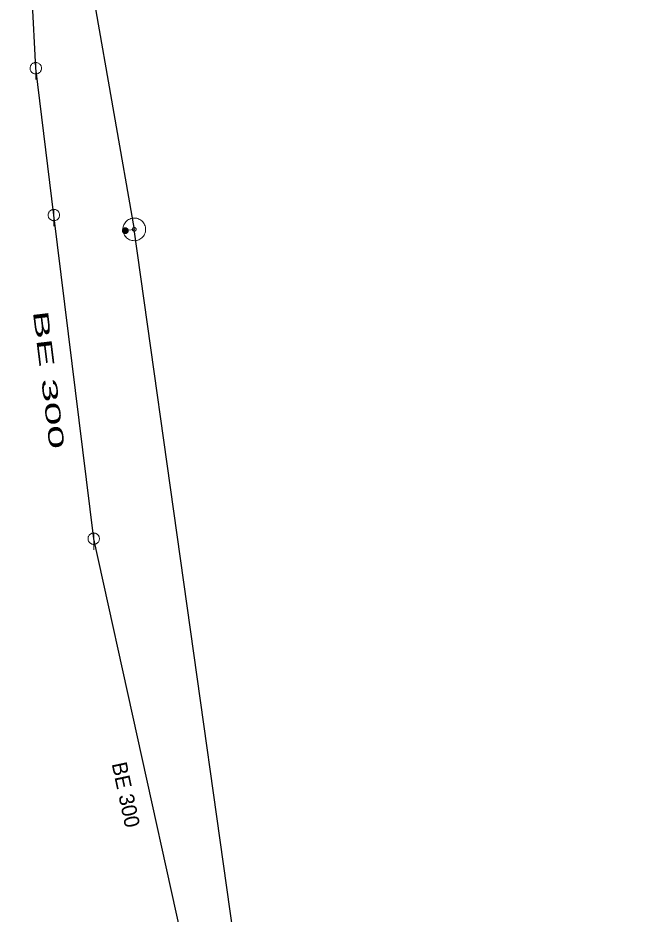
# Model space of a CAD drawing. Extents: x -687515 to -686506, y -974029 to -973461.
# Drawn here: x -687365.89 to -687338.06, y -973760.45 to -973720.93 of the extents above; entities that cross this region are included whole.
import ezdxf
from ezdxf.enums import TextEntityAlignment as Align

# ---------------------------------------------------------------- set-up
doc = ezdxf.new("R2010")
doc.units = 0
doc.header["$LTSCALE"] = 0.27
for name, color, linetype, lineweight in [('1', 7, 'Continuous', 13), ('14', 7, 'Continuous', 25), ('17', 7, 'Continuous', 25), ('22', 7, 'Continuous', 13), ('47', 7, 'Continuous', 13), ('9', 7, 'Continuous', 13)]:
    doc.layers.add(name, color=color, linetype=linetype, lineweight=lineweight)

msp = doc.modelspace()

# ---------------------------------------------------------------- linework, layer by layer
at = {"layer": '14'}
for p, q in [((-687365.103, -973723.149), (-687365.89, -973707.98)), ((-687364.305, -973729.623), (-687365.103, -973723.149)), ((-687362.547, -973743.895), (-687364.305, -973729.623)), ((-687356.89, -973769.55), (-687362.547, -973743.895))]:
    msp.add_line(p, q, dxfattribs=at)
at = {"layer": '14', "lineweight": 13}
msp.add_line((-687361.155, -973730.311), (-687360.759, -973730.255), dxfattribs=at)
at = {"layer": '17'}
for p in [(-687364.062, -973711.454), (-687338.055, -973891.483)]:
    msp.add_line(p, (-687360.759, -973730.255), dxfattribs=at)
at = {"layer": '22'}
for p, q in [((-687365.102, -973722.897), (-687365.103, -973723.641)), ((-687364.304, -973729.371), (-687364.305, -973730.115)), ((-687362.546, -973743.643), (-687362.547, -973744.387))]:
    msp.add_line(p, q, dxfattribs=at)
for points in [[(-687364.851, -973723.149), (-687364.852, -973723.123), (-687364.856, -973723.097), (-687364.862, -973723.071), (-687364.872, -973723.047), (-687364.884, -973723.023), (-687364.898, -973723.001), (-687364.915, -973722.98), (-687364.933, -973722.962), (-687364.954, -973722.945), (-687364.976, -973722.931), (-687365, -973722.919), (-687365.024, -973722.909), (-687365.05, -973722.903), (-687365.076, -973722.899), (-687365.102, -973722.897), (-687365.128, -973722.898), (-687365.154, -973722.902), (-687365.18, -973722.908), (-687365.205, -973722.918), (-687365.228, -973722.93), (-687365.25, -973722.944), (-687365.271, -973722.961), (-687365.289, -973722.979), (-687365.306, -973723), (-687365.32, -973723.022), (-687365.332, -973723.046), (-687365.342, -973723.07), (-687365.349, -973723.096), (-687365.353, -973723.122), (-687365.355, -973723.148), (-687365.354, -973723.174), (-687365.35, -973723.2), (-687365.343, -973723.226), (-687365.333, -973723.251), (-687365.321, -973723.274), (-687365.307, -973723.296), (-687365.29, -973723.317), (-687365.272, -973723.335), (-687365.251, -973723.352), (-687365.229, -973723.366), (-687365.206, -973723.378), (-687365.181, -973723.388), (-687365.155, -973723.395), (-687365.129, -973723.399), (-687365.103, -973723.401), (-687365.077, -973723.4), (-687365.051, -973723.396), (-687365.025, -973723.389), (-687365.001, -973723.379), (-687364.977, -973723.367), (-687364.955, -973723.353), (-687364.934, -973723.336), (-687364.916, -973723.318), (-687364.899, -973723.297), (-687364.885, -973723.275), (-687364.873, -973723.252), (-687364.863, -973723.227), (-687364.857, -973723.201), (-687364.853, -973723.175)], [(-687364.053, -973729.623), (-687364.054, -973729.597), (-687364.058, -973729.571), (-687364.064, -973729.545), (-687364.074, -973729.521), (-687364.086, -973729.497), (-687364.1, -973729.475), (-687364.117, -973729.454), (-687364.135, -973729.436), (-687364.156, -973729.419), (-687364.178, -973729.405), (-687364.202, -973729.393), (-687364.226, -973729.383), (-687364.252, -973729.377), (-687364.278, -973729.373), (-687364.304, -973729.371), (-687364.33, -973729.372), (-687364.356, -973729.376), (-687364.382, -973729.382), (-687364.407, -973729.392), (-687364.43, -973729.404), (-687364.452, -973729.418), (-687364.473, -973729.435), (-687364.491, -973729.453), (-687364.508, -973729.474), (-687364.522, -973729.496), (-687364.534, -973729.52), (-687364.544, -973729.544), (-687364.551, -973729.57), (-687364.555, -973729.596), (-687364.557, -973729.622), (-687364.556, -973729.648), (-687364.552, -973729.674), (-687364.545, -973729.7), (-687364.535, -973729.725), (-687364.523, -973729.748), (-687364.509, -973729.77), (-687364.492, -973729.791), (-687364.474, -973729.809), (-687364.453, -973729.826), (-687364.431, -973729.84), (-687364.408, -973729.852), (-687364.383, -973729.862), (-687364.357, -973729.869), (-687364.331, -973729.873), (-687364.305, -973729.875), (-687364.279, -973729.874), (-687364.253, -973729.87), (-687364.227, -973729.863), (-687364.203, -973729.853), (-687364.179, -973729.841), (-687364.157, -973729.827), (-687364.136, -973729.81), (-687364.118, -973729.792), (-687364.101, -973729.771), (-687364.087, -973729.749), (-687364.075, -973729.726), (-687364.065, -973729.701), (-687364.059, -973729.675), (-687364.055, -973729.649)], [(-687362.295, -973743.895), (-687362.296, -973743.869), (-687362.3, -973743.843), (-687362.306, -973743.817), (-687362.316, -973743.793), (-687362.328, -973743.769), (-687362.342, -973743.747), (-687362.359, -973743.726), (-687362.377, -973743.708), (-687362.398, -973743.691), (-687362.42, -973743.677), (-687362.444, -973743.665), (-687362.468, -973743.655), (-687362.494, -973743.649), (-687362.52, -973743.645), (-687362.546, -973743.643), (-687362.572, -973743.644), (-687362.598, -973743.648), (-687362.624, -973743.654), (-687362.649, -973743.664), (-687362.672, -973743.676), (-687362.694, -973743.69), (-687362.715, -973743.707), (-687362.733, -973743.725), (-687362.75, -973743.746), (-687362.764, -973743.768), (-687362.776, -973743.792), (-687362.786, -973743.816), (-687362.793, -973743.842), (-687362.797, -973743.868), (-687362.799, -973743.894), (-687362.798, -973743.92), (-687362.794, -973743.946), (-687362.787, -973743.972), (-687362.777, -973743.997), (-687362.765, -973744.02), (-687362.751, -973744.042), (-687362.734, -973744.063), (-687362.716, -973744.081), (-687362.695, -973744.098), (-687362.673, -973744.112), (-687362.65, -973744.124), (-687362.625, -973744.134), (-687362.599, -973744.141), (-687362.573, -973744.145), (-687362.547, -973744.147), (-687362.521, -973744.146), (-687362.495, -973744.142), (-687362.469, -973744.135), (-687362.445, -973744.125), (-687362.421, -973744.113), (-687362.399, -973744.099), (-687362.378, -973744.082), (-687362.36, -973744.064), (-687362.343, -973744.043), (-687362.329, -973744.021), (-687362.317, -973743.998), (-687362.307, -973743.973), (-687362.301, -973743.947), (-687362.297, -973743.921)]]:
    msp.add_lwpolyline(points, close=True, dxfattribs=at)
at = {"layer": '47'}
for points in [[(-687360.656, -973730.744), (-687360.606, -973730.73), (-687360.557, -973730.712), (-687360.51, -973730.688), (-687360.466, -973730.66), (-687360.425, -973730.627), (-687360.388, -973730.59), (-687360.356, -973730.549), (-687360.327, -973730.505), (-687360.303, -973730.459), (-687360.283, -973730.41), (-687360.27, -973730.36), (-687360.262, -973730.308), (-687360.259, -973730.256), (-687360.261, -973730.204), (-687360.269, -973730.152), (-687360.283, -973730.102), (-687360.301, -973730.053), (-687360.325, -973730.005), (-687360.353, -973729.962), (-687360.386, -973729.921), (-687360.423, -973729.884), (-687360.464, -973729.851), (-687360.508, -973729.822), (-687360.554, -973729.798), (-687360.603, -973729.779), (-687360.653, -973729.766), (-687360.705, -973729.757), (-687360.757, -973729.755), (-687360.809, -973729.757), (-687360.861, -973729.765), (-687360.911, -973729.779), (-687360.96, -973729.797), (-687361.008, -973729.82), (-687361.051, -973729.849), (-687361.092, -973729.882), (-687361.129, -973729.918), (-687361.163, -973729.959), (-687361.191, -973730.003), (-687361.215, -973730.05), (-687361.234, -973730.099), (-687361.247, -973730.149), (-687361.256, -973730.2), (-687361.258, -973730.253), (-687361.256, -973730.305), (-687361.248, -973730.357), (-687361.234, -973730.407), (-687361.216, -973730.456), (-687361.193, -973730.503), (-687361.164, -973730.547), (-687361.131, -973730.588), (-687361.095, -973730.625), (-687361.054, -973730.658), (-687361.01, -973730.686), (-687360.963, -973730.71), (-687360.914, -973730.73), (-687360.864, -973730.743), (-687360.813, -973730.751), (-687360.76, -973730.754), (-687360.708, -973730.752)], [(-687360.742, -973730.335), (-687360.733, -973730.333), (-687360.725, -973730.329), (-687360.718, -973730.326), (-687360.711, -973730.321), (-687360.704, -973730.316), (-687360.698, -973730.309), (-687360.692, -973730.303), (-687360.688, -973730.296), (-687360.684, -973730.288), (-687360.681, -973730.28), (-687360.678, -973730.271), (-687360.677, -973730.263), (-687360.677, -973730.255), (-687360.676, -973730.247), (-687360.678, -973730.238), (-687360.68, -973730.229), (-687360.684, -973730.221), (-687360.687, -973730.214), (-687360.692, -973730.207), (-687360.697, -973730.2), (-687360.704, -973730.194), (-687360.71, -973730.188), (-687360.717, -973730.184), (-687360.725, -973730.179), (-687360.733, -973730.177), (-687360.742, -973730.174), (-687360.75, -973730.173), (-687360.758, -973730.173), (-687360.766, -973730.172), (-687360.775, -973730.174), (-687360.784, -973730.176), (-687360.792, -973730.18), (-687360.799, -973730.183), (-687360.806, -973730.188), (-687360.813, -973730.193), (-687360.819, -973730.199), (-687360.825, -973730.206), (-687360.829, -973730.213), (-687360.834, -973730.221), (-687360.836, -973730.229), (-687360.839, -973730.238), (-687360.84, -973730.246), (-687360.84, -973730.254), (-687360.841, -973730.262), (-687360.839, -973730.271), (-687360.837, -973730.28), (-687360.833, -973730.288), (-687360.83, -973730.295), (-687360.825, -973730.302), (-687360.82, -973730.309), (-687360.814, -973730.315), (-687360.807, -973730.321), (-687360.8, -973730.325), (-687360.792, -973730.329), (-687360.784, -973730.332), (-687360.775, -973730.335), (-687360.767, -973730.336), (-687360.759, -973730.336), (-687360.751, -973730.337)]]:
    msp.add_lwpolyline(points, close=True, dxfattribs=at)
at = {"layer": '9'}
for points in [[(-687361.029, -973730.311), (-687361.03, -973730.298), (-687361.032, -973730.285), (-687361.035, -973730.272), (-687361.04, -973730.26), (-687361.046, -973730.248), (-687361.053, -973730.237), (-687361.061, -973730.227), (-687361.071, -973730.217), (-687361.081, -973730.209), (-687361.092, -973730.201), (-687361.104, -973730.196), (-687361.116, -973730.191), (-687361.129, -973730.188), (-687361.142, -973730.186), (-687361.155, -973730.184), (-687361.168, -973730.186), (-687361.181, -973730.188), (-687361.194, -973730.191), (-687361.206, -973730.196), (-687361.218, -973730.201), (-687361.229, -973730.209), (-687361.239, -973730.217), (-687361.249, -973730.227), (-687361.257, -973730.237), (-687361.264, -973730.248), (-687361.27, -973730.26), (-687361.275, -973730.272), (-687361.278, -973730.285), (-687361.28, -973730.298), (-687361.281, -973730.311), (-687361.28, -973730.324), (-687361.278, -973730.337), (-687361.275, -973730.35), (-687361.27, -973730.362), (-687361.264, -973730.374), (-687361.257, -973730.385), (-687361.249, -973730.395), (-687361.239, -973730.405), (-687361.229, -973730.413), (-687361.218, -973730.42), (-687361.206, -973730.426), (-687361.194, -973730.431), (-687361.181, -973730.434), (-687361.168, -973730.436), (-687361.155, -973730.437), (-687361.142, -973730.436), (-687361.129, -973730.434), (-687361.116, -973730.431), (-687361.104, -973730.426), (-687361.092, -973730.42), (-687361.081, -973730.413), (-687361.071, -973730.405), (-687361.061, -973730.395), (-687361.053, -973730.385), (-687361.046, -973730.374), (-687361.04, -973730.362), (-687361.035, -973730.35), (-687361.032, -973730.337), (-687361.03, -973730.324)], [(-687361.049, -973730.311), (-687361.049, -973730.299), (-687361.051, -973730.289), (-687361.054, -973730.277), (-687361.058, -973730.268), (-687361.063, -973730.258), (-687361.069, -973730.249), (-687361.076, -973730.24), (-687361.084, -973730.232), (-687361.093, -973730.225), (-687361.102, -973730.219), (-687361.112, -973730.214), (-687361.122, -973730.21), (-687361.133, -973730.206), (-687361.144, -973730.205), (-687361.155, -973730.205), (-687361.166, -973730.205), (-687361.177, -973730.206), (-687361.188, -973730.21), (-687361.198, -973730.214), (-687361.208, -973730.219), (-687361.217, -973730.225), (-687361.226, -973730.232), (-687361.234, -973730.24), (-687361.241, -973730.249), (-687361.247, -973730.258), (-687361.252, -973730.268), (-687361.256, -973730.277), (-687361.259, -973730.289), (-687361.261, -973730.299), (-687361.261, -973730.311), (-687361.261, -973730.322), (-687361.259, -973730.333), (-687361.256, -973730.344), (-687361.252, -973730.353), (-687361.247, -973730.364), (-687361.241, -973730.373), (-687361.234, -973730.382), (-687361.226, -973730.39), (-687361.217, -973730.397), (-687361.208, -973730.402), (-687361.198, -973730.407), (-687361.188, -973730.412), (-687361.177, -973730.415), (-687361.166, -973730.417), (-687361.155, -973730.417), (-687361.144, -973730.417), (-687361.133, -973730.415), (-687361.122, -973730.412), (-687361.112, -973730.407), (-687361.102, -973730.402), (-687361.093, -973730.397), (-687361.084, -973730.39), (-687361.076, -973730.382), (-687361.069, -973730.373), (-687361.063, -973730.364), (-687361.058, -973730.353), (-687361.054, -973730.344), (-687361.051, -973730.333), (-687361.049, -973730.322)], [(-687361.068, -973730.311), (-687361.069, -973730.302), (-687361.07, -973730.293), (-687361.073, -973730.284), (-687361.076, -973730.276), (-687361.08, -973730.268), (-687361.085, -973730.26), (-687361.091, -973730.253), (-687361.097, -973730.247), (-687361.104, -973730.241), (-687361.112, -973730.236), (-687361.12, -973730.232), (-687361.128, -973730.228), (-687361.137, -973730.226), (-687361.146, -973730.225), (-687361.155, -973730.223), (-687361.164, -973730.225), (-687361.173, -973730.226), (-687361.182, -973730.228), (-687361.19, -973730.232), (-687361.198, -973730.236), (-687361.206, -973730.241), (-687361.213, -973730.247), (-687361.219, -973730.253), (-687361.225, -973730.26), (-687361.23, -973730.268), (-687361.234, -973730.276), (-687361.237, -973730.284), (-687361.24, -973730.293), (-687361.241, -973730.302), (-687361.242, -973730.311), (-687361.241, -973730.32), (-687361.24, -973730.329), (-687361.237, -973730.338), (-687361.234, -973730.346), (-687361.23, -973730.353), (-687361.225, -973730.362), (-687361.219, -973730.369), (-687361.213, -973730.375), (-687361.206, -973730.38), (-687361.198, -973730.386), (-687361.19, -973730.39), (-687361.182, -973730.393), (-687361.173, -973730.396), (-687361.164, -973730.397), (-687361.155, -973730.398), (-687361.146, -973730.397), (-687361.137, -973730.396), (-687361.128, -973730.393), (-687361.12, -973730.39), (-687361.112, -973730.386), (-687361.104, -973730.38), (-687361.097, -973730.375), (-687361.091, -973730.369), (-687361.085, -973730.362), (-687361.08, -973730.353), (-687361.076, -973730.346), (-687361.073, -973730.338), (-687361.07, -973730.329), (-687361.069, -973730.32)], [(-687361.088, -973730.311), (-687361.088, -973730.304), (-687361.09, -973730.297), (-687361.091, -973730.29), (-687361.094, -973730.284), (-687361.097, -973730.277), (-687361.101, -973730.272), (-687361.105, -973730.266), (-687361.11, -973730.261), (-687361.116, -973730.257), (-687361.122, -973730.253), (-687361.128, -973730.25), (-687361.134, -973730.247), (-687361.141, -973730.246), (-687361.148, -973730.244), (-687361.155, -973730.244), (-687361.162, -973730.244), (-687361.169, -973730.246), (-687361.176, -973730.247), (-687361.182, -973730.25), (-687361.189, -973730.253), (-687361.194, -973730.257), (-687361.2, -973730.261), (-687361.205, -973730.266), (-687361.209, -973730.272), (-687361.213, -973730.277), (-687361.216, -973730.284), (-687361.219, -973730.29), (-687361.221, -973730.297), (-687361.222, -973730.304), (-687361.222, -973730.311), (-687361.222, -973730.318), (-687361.221, -973730.325), (-687361.219, -973730.331), (-687361.216, -973730.338), (-687361.213, -973730.345), (-687361.209, -973730.35), (-687361.205, -973730.356), (-687361.2, -973730.361), (-687361.194, -973730.365), (-687361.189, -973730.369), (-687361.182, -973730.372), (-687361.176, -973730.375), (-687361.169, -973730.377), (-687361.162, -973730.378), (-687361.155, -973730.378), (-687361.148, -973730.378), (-687361.141, -973730.377), (-687361.134, -973730.375), (-687361.128, -973730.372), (-687361.122, -973730.369), (-687361.116, -973730.365), (-687361.11, -973730.361), (-687361.105, -973730.356), (-687361.101, -973730.35), (-687361.097, -973730.345), (-687361.094, -973730.338), (-687361.091, -973730.331), (-687361.09, -973730.325), (-687361.088, -973730.318)], [(-687361.108, -973730.311), (-687361.108, -973730.306), (-687361.109, -973730.301), (-687361.11, -973730.296), (-687361.112, -973730.292), (-687361.114, -973730.287), (-687361.117, -973730.282), (-687361.12, -973730.28), (-687361.124, -973730.276), (-687361.127, -973730.273), (-687361.131, -973730.27), (-687361.136, -973730.268), (-687361.14, -973730.266), (-687361.145, -973730.265), (-687361.15, -973730.264), (-687361.155, -973730.264), (-687361.16, -973730.264), (-687361.165, -973730.265), (-687361.17, -973730.266), (-687361.174, -973730.268), (-687361.179, -973730.27), (-687361.183, -973730.273), (-687361.187, -973730.276), (-687361.19, -973730.28), (-687361.193, -973730.282), (-687361.196, -973730.287), (-687361.198, -973730.292), (-687361.2, -973730.296), (-687361.201, -973730.301), (-687361.202, -973730.306), (-687361.202, -973730.311), (-687361.202, -973730.316), (-687361.201, -973730.321), (-687361.2, -973730.326), (-687361.198, -973730.33), (-687361.196, -973730.335), (-687361.193, -973730.339), (-687361.19, -973730.343), (-687361.187, -973730.346), (-687361.183, -973730.348), (-687361.179, -973730.352), (-687361.174, -973730.353), (-687361.17, -973730.356), (-687361.165, -973730.357), (-687361.16, -973730.358), (-687361.155, -973730.358), (-687361.15, -973730.358), (-687361.145, -973730.357), (-687361.14, -973730.356), (-687361.136, -973730.353), (-687361.131, -973730.352), (-687361.127, -973730.348), (-687361.124, -973730.346), (-687361.12, -973730.343), (-687361.117, -973730.339), (-687361.114, -973730.335), (-687361.112, -973730.33), (-687361.11, -973730.326), (-687361.109, -973730.321), (-687361.108, -973730.316)], [(-687361.128, -973730.311), (-687361.128, -973730.308), (-687361.128, -973730.304), (-687361.129, -973730.303), (-687361.13, -973730.299), (-687361.131, -973730.297), (-687361.133, -973730.295), (-687361.135, -973730.293), (-687361.137, -973730.291), (-687361.139, -973730.289), (-687361.141, -973730.287), (-687361.144, -973730.286), (-687361.147, -973730.285), (-687361.149, -973730.284), (-687361.152, -973730.284), (-687361.155, -973730.284), (-687361.158, -973730.284), (-687361.161, -973730.284), (-687361.164, -973730.285), (-687361.166, -973730.286), (-687361.169, -973730.287), (-687361.171, -973730.289), (-687361.174, -973730.291), (-687361.176, -973730.293), (-687361.177, -973730.295), (-687361.179, -973730.297), (-687361.18, -973730.299), (-687361.181, -973730.303), (-687361.182, -973730.304), (-687361.182, -973730.308), (-687361.183, -973730.311), (-687361.182, -973730.314), (-687361.182, -973730.317), (-687361.181, -973730.32), (-687361.18, -973730.322), (-687361.179, -973730.325), (-687361.177, -973730.326), (-687361.176, -973730.33), (-687361.174, -973730.331), (-687361.171, -973730.333), (-687361.169, -973730.335), (-687361.166, -973730.336), (-687361.164, -973730.337), (-687361.161, -973730.338), (-687361.158, -973730.338), (-687361.155, -973730.339), (-687361.152, -973730.338), (-687361.149, -973730.338), (-687361.147, -973730.337), (-687361.144, -973730.336), (-687361.141, -973730.335), (-687361.139, -973730.333), (-687361.137, -973730.331), (-687361.135, -973730.33), (-687361.133, -973730.326), (-687361.131, -973730.325), (-687361.13, -973730.322), (-687361.129, -973730.32), (-687361.128, -973730.317), (-687361.128, -973730.314)], [(-687361.147, -973730.311), (-687361.147, -973730.309), (-687361.147, -973730.309), (-687361.148, -973730.309), (-687361.148, -973730.308), (-687361.148, -973730.307), (-687361.149, -973730.306), (-687361.149, -973730.306), (-687361.15, -973730.304), (-687361.15, -973730.304), (-687361.151, -973730.304), (-687361.152, -973730.304), (-687361.153, -973730.304), (-687361.153, -973730.303), (-687361.154, -973730.303), (-687361.155, -973730.303), (-687361.156, -973730.303), (-687361.157, -973730.303), (-687361.157, -973730.304), (-687361.158, -973730.304), (-687361.159, -973730.304), (-687361.16, -973730.304), (-687361.16, -973730.304), (-687361.161, -973730.306), (-687361.161, -973730.306), (-687361.162, -973730.307), (-687361.162, -973730.308), (-687361.163, -973730.309), (-687361.163, -973730.309), (-687361.163, -973730.309), (-687361.163, -973730.311), (-687361.163, -973730.312), (-687361.163, -973730.313), (-687361.163, -973730.313), (-687361.162, -973730.314), (-687361.162, -973730.315), (-687361.161, -973730.316), (-687361.161, -973730.316), (-687361.16, -973730.317), (-687361.16, -973730.317), (-687361.159, -973730.318), (-687361.158, -973730.318), (-687361.157, -973730.319), (-687361.157, -973730.319), (-687361.156, -973730.319), (-687361.155, -973730.319), (-687361.154, -973730.319), (-687361.153, -973730.319), (-687361.153, -973730.319), (-687361.152, -973730.318), (-687361.151, -973730.318), (-687361.15, -973730.317), (-687361.15, -973730.317), (-687361.149, -973730.316), (-687361.149, -973730.316), (-687361.148, -973730.315), (-687361.148, -973730.314), (-687361.148, -973730.313), (-687361.147, -973730.313), (-687361.147, -973730.312)]]:
    msp.add_lwpolyline(points, close=True, dxfattribs=at)

# ---------------------------------------------------------------- texts
at = {"layer": '1', "width": 2.1}
msp.add_text('BE 300', height=0.6667, rotation=277, dxfattribs=at).set_placement((-687364.86, -973736.923), align=Align.CENTER)
at = {"layer": '1'}
msp.add_text('BE 300', height=0.6667, rotation=282, dxfattribs=at).set_placement((-687361.454, -973755.251), align=Align.CENTER)

doc.saveas('drawing.dxf')
